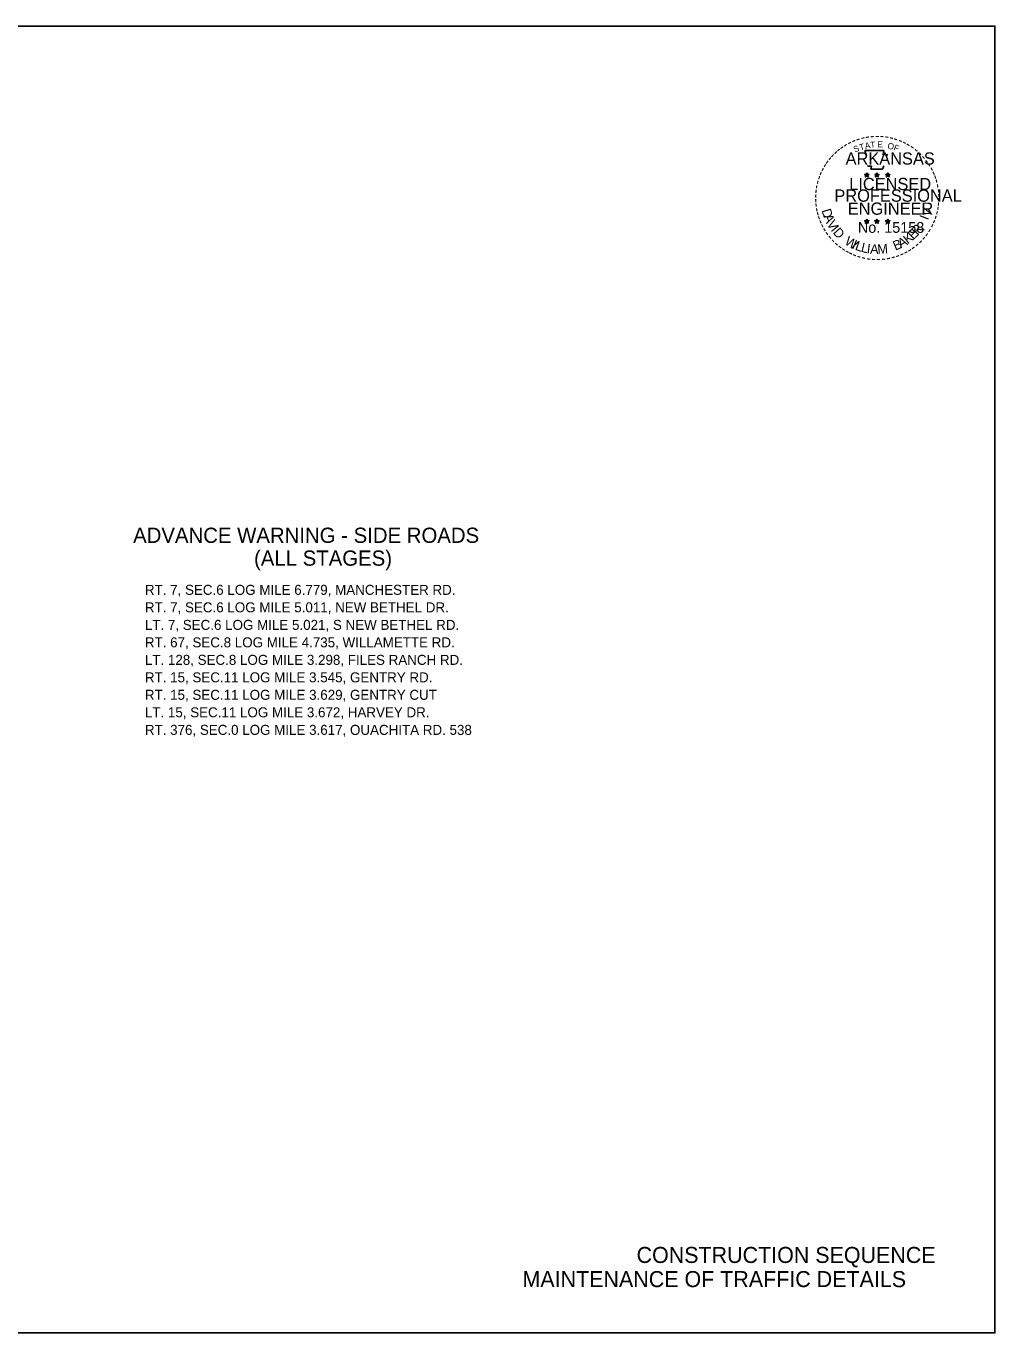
# Model space of a CAD drawing. Extents: x 1416408 to 1429341, y 372694 to 383211.
# Drawn here: x 1427679 to 1429003, y 375362 to 377148 of the extents above; entities that cross this region are included whole.
import ezdxf

# ---------------------------------------------------------------- set-up
doc = ezdxf.new("R2010")
doc.units = 0
for name, color, linetype in [('Default', 7, 'Continuous'), ('DSN_DRFT_Junk-No-Plot', 7, 'Continuous'), ('R_Border Notes', 7, 'Continuous'), ('R_Border PE', 7, 'Continuous'), ('R_Draft', 7, 'Continuous')]:
    doc.layers.add(name, color=color, linetype=linetype)

msp = doc.modelspace()

# ---------------------------------------------------------------- linework, layer by layer
at = {"layer": 'Default'}
msp.add_lwpolyline([(1426243.1, 377147.9), (1426243.1, 375361.9), (1429003.4, 375361.9), (1429003.4, 377147.9)], close=True, dxfattribs=at)
msp.add_lwpolyline([(1426243.1, 377147.9), (1426243.1, 375361.9), (1429003.4, 375361.9), (1429003.4, 377147.9)], close=True, dxfattribs=at)
at = {"layer": 'DSN_DRFT_Junk-No-Plot'}
msp.add_lwpolyline([(1426243.1, 377147.9), (1429003.4, 377147.9), (1429003.4, 375361.9), (1426243.1, 375361.9)], close=True, dxfattribs=at)
at = {"layer": 'R_Border PE'}
for p, q in [((1428825.3, 376945.2), (1428828.2, 376944.3)), ((1428825.3, 376945.2), (1428827.4, 376944.9)), ((1428825.3, 376945.2), (1428827.3, 376944.2)), ((1428826.4, 376941.8), (1428828.2, 376944.3)), ((1428826.4, 376941.8), (1428827.5, 376943.9)), ((1428828.2, 376947.4), (1428827.9, 376945.3)), ((1428828.2, 376944.3), (1428828.2, 376947.4)), ((1428828.2, 376947.4), (1428828.6, 376945.3)), ((1428831.1, 376945.2), (1428828.2, 376944.3)), ((1428830, 376941.8), (1428828.2, 376944.3)), ((1428831.1, 376945.2), (1428828.7, 376944.8)), ((1428830, 376941.8), (1428828.9, 376944.3)), ((1428831.1, 376945.2), (1428829.4, 376944.4)), ((1428839.3, 376945.2), (1428842.2, 376944.3)), ((1428839.3, 376945.2), (1428841.4, 376944.9)), ((1428839.3, 376945.2), (1428841.3, 376944.2)), ((1428840.4, 376941.8), (1428842.2, 376944.3)), ((1428840.4, 376941.8), (1428841.5, 376943.9)), ((1428842.2, 376947.4), (1428841.9, 376945.3)), ((1428842.2, 376944.3), (1428842.2, 376947.4)), ((1428842.2, 376947.4), (1428842.6, 376945.3)), ((1428845.1, 376945.2), (1428842.2, 376944.3)), ((1428844, 376941.8), (1428842.2, 376944.3)), ((1428845.1, 376945.2), (1428842.7, 376944.8)), ((1428844, 376941.8), (1428842.8, 376944.3)), ((1428845.1, 376945.2), (1428843.4, 376944.4)), ((1428854.1, 376945.1), (1428857, 376944.2)), ((1428854.1, 376945.1), (1428856.2, 376944.8)), ((1428854.1, 376945.1), (1428856, 376944.1)), ((1428855.2, 376941.7), (1428857, 376944.2)), ((1428855.2, 376941.7), (1428856.2, 376943.8)), ((1428857, 376947.3), (1428856.6, 376945.2)), ((1428857, 376944.2), (1428857, 376947.3)), ((1428857, 376947.3), (1428857.4, 376945.2)), ((1428859.9, 376945.1), (1428857, 376944.2)), ((1428858.8, 376941.7), (1428857, 376944.2)), ((1428859.9, 376945.1), (1428857.5, 376944.7)), ((1428858.8, 376941.7), (1428857.6, 376944.2)), ((1428859.9, 376945.1), (1428858.2, 376944.3)), ((1428826.4, 376941.8), (1428828.2, 376943.6)), ((1428830, 376941.8), (1428828.2, 376943.6)), ((1428840.4, 376941.8), (1428842.2, 376943.6)), ((1428844, 376941.8), (1428842.2, 376943.6)), ((1428855.2, 376941.7), (1428857, 376943.5)), ((1428858.8, 376941.7), (1428857, 376943.5)), ((1428825.3, 376881.8), (1428828.2, 376880.9)), ((1428825.3, 376881.8), (1428827.4, 376881.5)), ((1428825.3, 376881.8), (1428827.3, 376880.8)), ((1428826.4, 376878.4), (1428828.2, 376880.9)), ((1428826.4, 376878.4), (1428827.4, 376880.5)), ((1428826.4, 376878.4), (1428828.2, 376880.2)), ((1428828.2, 376884), (1428827.8, 376881.9)), ((1428828.2, 376880.9), (1428828.2, 376884)), ((1428828.2, 376884), (1428828.6, 376881.9)), ((1428831.1, 376881.8), (1428828.2, 376880.9)), ((1428830, 376878.4), (1428828.2, 376880.9)), ((1428830, 376878.4), (1428828.2, 376880.2)), ((1428831.1, 376881.8), (1428828.7, 376881.4)), ((1428830, 376878.4), (1428828.8, 376880.9)), ((1428831.1, 376881.8), (1428829.4, 376881)), ((1428839.2, 376881.8), (1428842.2, 376880.9)), ((1428839.2, 376881.8), (1428841.4, 376881.5)), ((1428839.2, 376881.8), (1428841.2, 376880.8)), ((1428840.4, 376878.4), (1428842.2, 376880.9)), ((1428840.4, 376878.4), (1428841.4, 376880.5)), ((1428840.4, 376878.4), (1428842.1, 376880.2)), ((1428842.2, 376884), (1428841.8, 376881.9)), ((1428843.9, 376878.4), (1428842.1, 376880.2)), ((1428842.2, 376880.9), (1428842.2, 376884)), ((1428842.2, 376884), (1428842.6, 376881.9)), ((1428845.1, 376881.8), (1428842.2, 376880.9)), ((1428843.9, 376878.4), (1428842.2, 376880.9)), ((1428845.1, 376881.8), (1428842.7, 376881.4)), ((1428843.9, 376878.4), (1428842.8, 376880.9)), ((1428845.1, 376881.8), (1428843.4, 376881)), ((1428854, 376881.8), (1428857, 376880.8)), ((1428854, 376881.8), (1428856.2, 376881.4)), ((1428854, 376881.8), (1428856, 376880.7)), ((1428855.1, 376878.3), (1428857, 376880.8)), ((1428855.1, 376878.3), (1428856.2, 376880.4)), ((1428855.1, 376878.3), (1428856.9, 376880.2)), ((1428857, 376883.9), (1428856.6, 376881.8)), ((1428858.7, 376878.3), (1428856.9, 376880.1)), ((1428857, 376880.8), (1428857, 376883.9)), ((1428857, 376883.9), (1428857.4, 376881.8)), ((1428859.9, 376881.8), (1428857, 376880.8)), ((1428858.7, 376878.3), (1428857, 376880.8)), ((1428859.9, 376881.8), (1428857.5, 376881.3)), ((1428858.7, 376878.3), (1428857.6, 376880.8)), ((1428859.9, 376881.8), (1428858.2, 376880.9))]:
    msp.add_line(p, q, dxfattribs=at)
for points in [[(1428825.6, 376977.7), (1428827.9, 376970.8)], [(1428855, 376970), (1428856.2, 376972.4), (1428850.5, 376972.2), (1428851.7, 376977.7), (1428825.6, 376977.7)], [(1428828.2, 376947.4), (1428830, 376941.8), (1428825.3, 376945.2), (1428831.1, 376945.2), (1428826.4, 376941.8), (1428828.2, 376947.4)], [(1428829.8, 376957.4), (1428829.8, 376956.7), (1428834.5, 376956.5), (1428834, 376952.6), (1428849.7, 376952.6), (1428851.4, 376957.1)], [(1428842.2, 376947.4), (1428844, 376941.8), (1428839.3, 376945.2), (1428845.1, 376945.2), (1428840.4, 376941.8), (1428842.2, 376947.4)], [(1428857, 376947.3), (1428858.8, 376941.7), (1428854.1, 376945.1), (1428859.9, 376945.1), (1428855.2, 376941.7), (1428857, 376947.3)], [(1428828.2, 376884), (1428830, 376878.4), (1428825.3, 376881.8), (1428831.1, 376881.8), (1428826.4, 376878.4), (1428828.2, 376884)], [(1428842.2, 376884), (1428843.9, 376878.4), (1428839.2, 376881.8), (1428845.1, 376881.8), (1428840.4, 376878.4), (1428842.2, 376884)], [(1428857, 376883.9), (1428858.7, 376878.3), (1428854, 376881.8), (1428859.9, 376881.8), (1428855.1, 376878.3), (1428857, 376883.9)]]:
    msp.add_lwpolyline(points, dxfattribs=at)
for centre, radius in [((1428828.2, 376944.3), 1.44), ((1428828.2, 376944.3), 1.21), ((1428828.2, 376944.3), 0.969), ((1428828.2, 376944.3), 0.83), ((1428828.2, 376944.3), 0.626), ((1428828.2, 376944.3), 0.415), ((1428828.2, 376944.3), 0.248), ((1428842.2, 376944.3), 1.44), ((1428842.2, 376944.3), 1.21), ((1428842.2, 376944.3), 0.969), ((1428842.2, 376944.3), 0.83), ((1428842.2, 376944.3), 0.626), ((1428842.2, 376944.3), 0.415), ((1428842.2, 376944.3), 0.248), ((1428857, 376944.2), 1.44), ((1428857, 376944.2), 1.21), ((1428857, 376944.2), 0.969), ((1428857, 376944.2), 0.83), ((1428857, 376944.2), 0.626), ((1428857, 376944.2), 0.415), ((1428857, 376944.2), 0.248), ((1428828.2, 376880.9), 1.44), ((1428828.2, 376880.9), 1.21), ((1428828.2, 376880.9), 0.969), ((1428828.2, 376880.9), 0.83), ((1428828.2, 376880.9), 0.626), ((1428828.2, 376880.9), 0.415), ((1428828.2, 376880.9), 0.248), ((1428842.2, 376880.9), 1.44), ((1428842.2, 376880.9), 1.21), ((1428842.2, 376880.9), 0.969), ((1428842.2, 376880.9), 0.83), ((1428842.2, 376880.9), 0.626), ((1428842.2, 376880.9), 0.415), ((1428842.2, 376880.9), 0.248), ((1428856.9, 376880.8), 1.44), ((1428856.9, 376880.8), 1.21), ((1428856.9, 376880.8), 0.969), ((1428856.9, 376880.8), 0.83), ((1428856.9, 376880.8), 0.626), ((1428856.9, 376880.8), 0.415), ((1428856.9, 376880.8), 0.248)]:
    msp.add_circle(centre, radius, dxfattribs=at)

# ---------------------------------------------------------------- texts
at = {"layer": 'R_Border Notes'}
for s, p in [('CONSTRUCTION SEQUENCE', (1428513.6, 375457.4)), ('MAINTENANCE OF TRAFFIC DETAILS', (1428357.6, 375424.4))]:
    msp.add_text(s, height=21.92, dxfattribs=at).set_placement(p)
at = {"layer": 'R_Border PE'}
for s, height, rotation, p in [('-', 13.4, 10.2193, (1428827.1, 376990.5)), ('-', 13.4, 5.8968, (1428833.2, 376991.4)), ('-', 13.4, 0.1862, (1428839.7, 376992)), ('-', 13.4, 357.743, (1428845.7, 376991.9)), ('-', 13.4, 38.9507, (1428790.7, 376972.7)), ('-', 13.4, 36.2317, (1428794.7, 376975.8)), ('-', 13.4, 34.0636, (1428799.6, 376979.1)), ('-', 13.4, 28.7918, (1428804.6, 376982.2)), ('-', 13.4, 24.3072, (1428809.9, 376984.9)), ('S', 8.37, 21.594, (1428811.9, 376975)), ('-', 13.4, 19.1761, (1428815.2, 376987.1)), ('T', 8.37, 16.4036, (1428819.5, 376977.8)), ('-', 13.4, 13.6302, (1428821.4, 376989.2)), ('A', 8.37, 11.2132, (1428826.4, 376979.9)), ('T', 8.37, 6.0228, (1428833.5, 376981.3)), ('E', 8.37, 0.8323, (1428842.8, 376982.2)), ('-', 13.4, 352.1617, (1428852, 376991.5)), ('O', 8.37, 350.4515, (1428856.2, 376980.4)), ('-', 13.4, 347.2049, (1428858, 376990.5)), ('F', 8.37, 340.0707, (1428864.2, 376978.5)), ('-', 13.4, 342.3362, (1428863.3, 376989.2)), ('-', 13.4, 337.8551, (1428869.5, 376987.3)), ('-', 13.4, 334.1211, (1428874.7, 376985.1)), ('-', 13.4, 329.6409, (1428879.6, 376982.7)), ('-', 13.4, 325.8627, (1428885, 376979.7)), ('-', 13.4, 320.5297, (1428890.1, 376976.1)), ('-', 13.4, 54.2325, (1428776.5, 376956.4)), ('-', 13.4, 50.6142, (1428780, 376961.1)), ('-', 13.4, 48.4231, (1428783.4, 376965.2)), ('-', 13.4, 42.9622, (1428787.1, 376969.2)), ('-', 13.4, 315.5786, (1428895.1, 376972)), ('-', 13.4, 309.8797, (1428899.9, 376967.4)), ('-', 13.4, 306.6522, (1428904.2, 376962.4)), ('-', 13.4, 67.7743, (1428769, 376941.7)), ('-', 13.4, 62.8713, (1428771.2, 376946.8)), ('-', 13.4, 58.0706, (1428773.8, 376952)), ('-', 11.7, 303.6753, (1428908.3, 376957.6)), ('-', 13.4, 299.6684, (1428911, 376952.6)), ('-', 13.4, 294.6628, (1428913.7, 376947.4)), ('-', 13.4, 290.5728, (1428915.9, 376942.6)), ('-', 13.4, 81.2013, (1428764.4, 376924.5)), ('-', 13.4, 75.461, (1428765.5, 376930.4)), ('-', 13.4, 72.3945, (1428767.2, 376936.4)), ('-', 13.4, 285.1233, (1428917.8, 376937.7)), ('-', 13.4, 280.5493, (1428919.5, 376931.5)), ('-', 13.4, 94.1959, (1428763.9, 376906.7)), ('-', 13.4, 89.0622, (1428763.6, 376912.8)), ('-', 13.4, 85.1863, (1428763.8, 376918.7)), ('-', 13.4, 276.5962, (1428920.8, 376925.1)), ('-', 13.4, 274.3301, (1428921.3, 376919.1)), ('-', 13.4, 269.9407, (1428921.6, 376913.8)), ('-', 13.4, 98.9479, (1428764.5, 376901.2)), ('-', 13.4, 101.7149, (1428765.6, 376895)), ('-', 13.4, 105.4578, (1428767, 376890)), ('D', 12.9, 286.2848, (1428766.4, 376896.2)), ('V', 12.9, 72.6573, (1428913.6, 376886.5)), ('-', 13.4, 255.7626, (1428920, 376897)), ('-', 13.4, 260.9953, (1428920.9, 376902.7)), ('-', 13.4, 263.5172, (1428921.5, 376908.2)), ('-', 13.4, 109.0874, (1428768.8, 376884.8)), ('-', 13.4, 114.0643, (1428770.9, 376879.8)), ('-', 13.4, 115.7289, (1428773.4, 376874.6)), ('A', 12.9, 292.7835, (1428768.8, 376887.8)), ('V', 12.9, 300.7936, (1428773.1, 376877.9)), ('I', 12.9, 308.3502, (1428778.4, 376869.2)), ('D', 12.9, 311.9774, (1428781.3, 376865.3)), ('R', 12.9, 50.3651, (1428898, 376861.1)), ('I', 12.9, 69.0301, (1428911.8, 376882)), (',', 12.9, 57.4684, (1428904, 376868.5)), ('-', 13.4, 244.6197, (1428914.4, 376880.1)), ('-', 13.4, 247.8887, (1428916.6, 376885.4)), ('-', 13.4, 252.8681, (1428918.4, 376891)), ('-', 13.4, 120.4471, (1428776.4, 376869.7)), ('-', 13.4, 125.8934, (1428779.8, 376865)), ('-', 13.4, 130.7181, (1428783.7, 376860.4)), ('-', 13.4, 134.2238, (1428788, 376855.8)), ('W', 12.9, 328.0731, (1428797, 376850.6)), ('I', 12.9, 336.6877, (1428807, 376844.6)), ('B', 12.9, 22.8589, (1428867.3, 376841)), ('A', 12.9, 28.9042, (1428874.8, 376844.1)), ('K', 12.9, 36.9143, (1428884.2, 376849.4)), ('E', 12.9, 44.0175, (1428891.8, 376855.2)), ('-', 13.4, 225.7653, (1428900.1, 376858.9)), ('-', 13.4, 231.2538, (1428904.1, 376863.6)), ('-', 13.4, 233.8452, (1428907.7, 376868.3)), ('-', 13.4, 239.0712, (1428911.1, 376873.8)), ('-', 13.4, 138.9338, (1428792.4, 376851.9)), ('-', 13.4, 144.6463, (1428797.1, 376848.5)), ('-', 13.4, 148.0898, (1428801.8, 376845.4)), ('-', 13.4, 151.5704, (1428806.6, 376842.7)), ('-', 13.4, 154.6002, (1428811, 376840.6)), ('L', 12.9, 340.3149, (1428811.4, 376842.6)), ('L', 12.9, 346.6625, (1428819.5, 376839.7)), ('I', 12.9, 353.0101, (1428827.8, 376837.7)), ('A', 12.9, 356.6373, (1428832.6, 376837)), ('M', 12.9, 4.6473, (1428843.3, 376836.5)), ('-', 13.4, 204.2516, (1428876.8, 376841.9)), ('-', 13.4, 207.3568, (1428882, 376844.5)), ('-', 13.4, 212.2491, (1428886.7, 376847.4)), ('-', 13.4, 215.7363, (1428891.1, 376850.7)), ('-', 13.4, 221.0851, (1428895.7, 376854.6)), ('-', 13.4, 158.5612, (1428816.2, 376838.5)), ('-', 13.4, 162.7983, (1428821.9, 376836.7)), ('-', 13.4, 167.5555, (1428827.9, 376835.4)), ('-', 13.4, 173.1155, (1428834.4, 376834.4)), ('-', 13.4, 176.5183, (1428840.7, 376834)), ('-', 13.4, 181.5918, (1428846.9, 376834.1)), ('-', 13.4, 185.8167, (1428853.7, 376834.8)), ('-', 13.4, 191.2858, (1428859.8, 376835.9)), ('-', 13.4, 195.4743, (1428865.9, 376837.6)), ('-', 13.4, 199.4643, (1428871.5, 376839.5))]:
    msp.add_text(s, height=height, rotation=rotation, dxfattribs=at).set_placement(p)
for s, height, p in [('ARKANSAS', 16.74, (1428799.3, 376958.6)), ('LICENSED', 16.74, (1428804.3, 376923.8)), ('PROFESSIONAL', 16.744, (1428784, 376907.9)), ('ENGINEER', 16.74, (1428802.3, 376890.1)), ('No. 15158', 14.71, (1428816.1, 376865.4)), ('AAMU', 0.000167, (1428841.6, 376836.5))]:
    msp.add_text(s, height=height, dxfattribs=at).set_placement(p)
at = {"layer": 'R_Draft'}
for s, height, p in [('ADVANCE WARNING - SIDE ROADS', 20.805, (1427825.4, 376441.6)), ('(ALL STAGES)', 20.805, (1427990.7, 376410.4)), ('RT. 7, SEC.6 LOG MILE 6.779, MANCHESTER RD.', 13.668, (1427841.5, 376370.6)), ('RT. 7, SEC.6 LOG MILE 5.011, NEW BETHEL DR.', 13.668, (1427841.5, 376346.7)), ('LT. 7, SEC.6 LOG MILE 5.021, S NEW BETHEL RD.', 13.668, (1427841.5, 376322.7)), ('RT. 67, SEC.8 LOG MILE 4.735, WILLAMETTE RD. ', 13.668, (1427841.5, 376298.8)), ('LT. 128, SEC.8 LOG MILE 3.298, FILES RANCH RD.', 13.668, (1427841.5, 376274.9)), ('RT. 15, SEC.11 LOG MILE 3.545, GENTRY RD.', 13.668, (1427841.5, 376251)), ('RT. 15, SEC.11 LOG MILE 3.629, GENTRY CUT', 13.668, (1427841.5, 376227.1)), ('LT. 15, SEC.11 LOG MILE 3.672, HARVEY DR.', 13.668, (1427841.5, 376203.2)), ('RT. 376, SEC.0 LOG MILE 3.617, OUACHITA RD. 538', 13.668, (1427841.5, 376179.2))]:
    msp.add_text(s, height=height, dxfattribs=at).set_placement(p)

doc.saveas('drawing.dxf')
